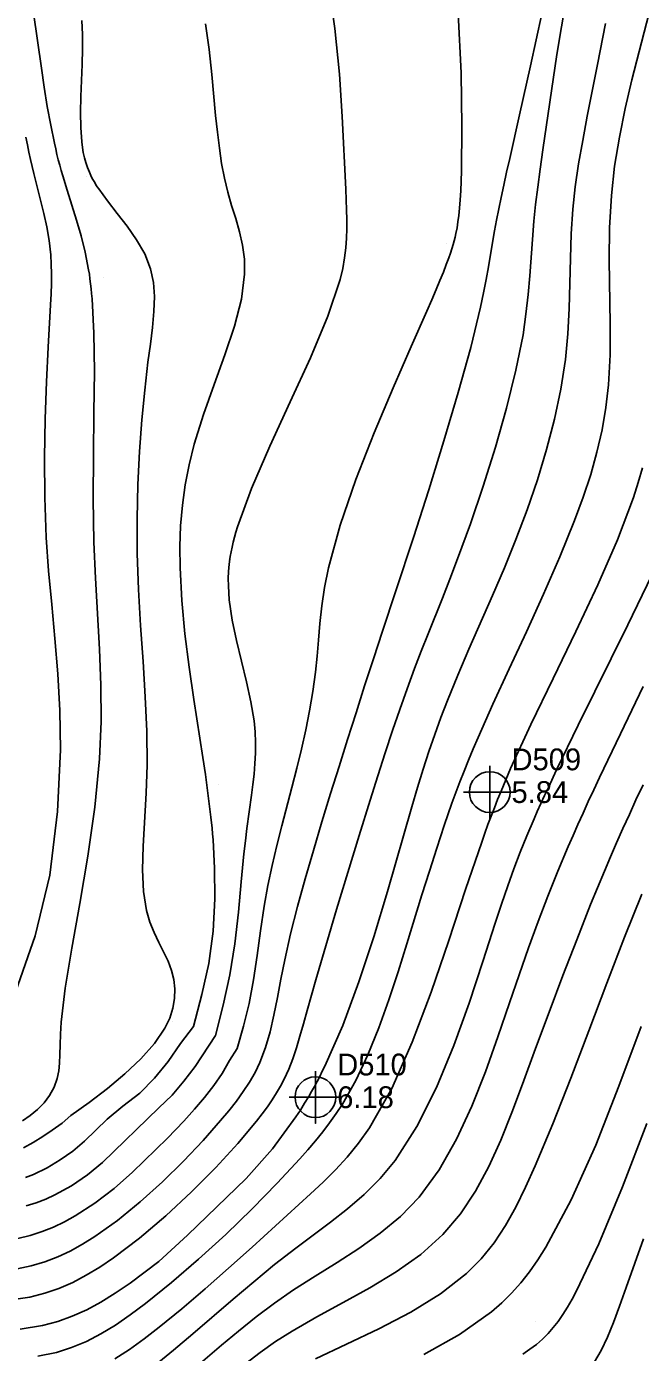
# Model space of a CAD drawing. Extents: x 2356077 to 2359823, y 225951 to 227822.
# Drawn here: x 2356980.4 to 2357050.9, y 226841 to 226993.2 of the extents above; entities that cross this region are included whole.
import ezdxf

# ---------------------------------------------------------------- set-up
doc = ezdxf.new("R2010")
doc.units = 0
for name, color, linetype in [('DTM Contours Major', 7, 'Continuous'), ('DTM Contours Minor', 7, 'Continuous'), ('Exist DTM Regular Point CELL', 7, 'Continuous'), ('Exist DTM Regular Point Cogo Elevation', 7, 'Continuous'), ('Exist DTM Regular Point Cogo Number', 7, 'Continuous'), ('PH Exist DTM Point', 7, 'Continuous')]:
    doc.layers.add(name, color=color, linetype=linetype)

msp = doc.modelspace()

# ---------------------------------------------------------------- linework, layer by layer
at = {"layer": 'DTM Contours Major'}
for points in [[(2357015.01, 226998.28), (2357015.79, 226992.92), (2357016.3, 226987.69), (2357016.61, 226982.83), (2357017.04, 226974.49), (2357017.09, 226973.29), (2357017.13, 226972.14), (2357017.15, 226971.02), (2357017.15, 226969.95), (2357017.12, 226968.88), (2357017.04, 226967.77), (2357016.9, 226966.62), (2357016.68, 226965.41), (2357016.38, 226964.12), (2357014.97, 226959.92), (2357012.97, 226955.16), (2357010.66, 226950.1), (2357008.32, 226945), (2357006.2, 226940.13), (2357004.6, 226935.75), (2357004.42, 226935.14), (2357004.25, 226934.55), (2357004.1, 226933.98), (2357003.98, 226933.42), (2357003.86, 226932.87), (2357003.77, 226932.33), (2357003.65, 226931.47), (2357003.58, 226930.63), (2357003.54, 226929.81), (2357003.55, 226928.99), (2357003.59, 226928.17), (2357003.66, 226927.36), (2357004, 226925.04), (2357004.49, 226922.69), (2357005.06, 226920.32), (2357005.64, 226917.97), (2357006.15, 226915.68), (2357006.51, 226913.48), (2357006.63, 226912.21), (2357006.68, 226910.98), (2357006.67, 226909.77), (2357006.61, 226908.57), (2357006.51, 226907.37), (2357006.38, 226906.16), (2357006.22, 226904.96), (2357005.69, 226901.12), (2357005.51, 226899.71), (2357005.34, 226898.22), (2357005.03, 226894.99), (2357004.71, 226891.51), (2357004.3, 226887.91), (2357003.73, 226884.32), (2357002.94, 226880.87), (2357002.07, 226877.37), (2356999.72, 226873.83), (2356998.45, 226872.12), (2356997.09, 226870.51), (2356995.58, 226869.08), (2356989.1, 226862.81), (2356987.37, 226861.39), (2356985.55, 226860.14), (2356983.64, 226859.08), (2356982.58, 226858.59), (2356981.49, 226858.17), (2356980.34, 226857.81)], [(2357052.41, 226996.83), (2357050.72, 226990.3), (2357049.9, 226987.04), (2357049.13, 226983.76), (2357048.45, 226980.45), (2357047.91, 226977.12), (2357047.53, 226973.76), (2357047.33, 226970.06), (2357047.3, 226966.36), (2357047.4, 226959.05), (2357047.38, 226955.5), (2357047.2, 226952.06), (2357046.9, 226949.44), (2357046.46, 226946.88), (2357045.88, 226944.33), (2357045.16, 226941.77), (2357044.3, 226939.16), (2357043.31, 226936.48), (2357041.63, 226932.31), (2357039.75, 226928.02), (2357037.77, 226923.7), (2357035.8, 226919.45), (2357033.92, 226915.38), (2357032.23, 226911.59), (2357031.66, 226910.26), (2357031.13, 226908.97), (2357030.62, 226907.72), (2357030.14, 226906.48), (2357029.68, 226905.25), (2357029.23, 226904.02), (2357028.34, 226901.49), (2357027.48, 226898.89), (2357026.63, 226896.23), (2357025.78, 226893.51), (2357024.05, 226887.91), (2357023.04, 226884.69), (2357021.98, 226881.45), (2357020.83, 226878.25), (2357019.58, 226875.16), (2357018.19, 226872.22), (2357016.65, 226869.5), (2357015.93, 226868.41), (2357015.18, 226867.35), (2357014.39, 226866.32), (2357013.56, 226865.3), (2357012.69, 226864.27), (2357011.77, 226863.23), (2357009.15, 226860.41), (2357006.28, 226857.49), (2357003.25, 226854.55), (2357000.14, 226851.7), (2356997.04, 226849.02), (2356994.03, 226846.6), (2356992.29, 226845.3), (2356990.59, 226844.15), (2356988.92, 226843.13), (2356987.25, 226842.26), (2356985.55, 226841.55), (2356983.81, 226841), (2356981.67, 226840.56)], [(2357051.03, 226893.61), (2357049.06, 226888.66), (2357047.03, 226883.36), (2357044.95, 226877.9), (2357042.86, 226872.46), (2357040.8, 226867.24), (2357038.79, 226862.43), (2357037.68, 226859.96), (2357036.56, 226857.67), (2357035.37, 226855.55), (2357034.06, 226853.58), (2357032.59, 226851.76), (2357030.91, 226850.07), (2357027.91, 226847.73), (2357024.49, 226845.63), (2357020.84, 226843.72), (2357017.13, 226841.94), (2357013.54, 226840.25)]]:
    msp.add_lwpolyline(points, dxfattribs=at)
at = {"layer": 'DTM Contours Minor'}
for points in [[(2357042.35, 226996.36), (2357041.29, 226989.94), (2357039.68, 226979.01), (2357039.36, 226976.79), (2357039.08, 226974.71), (2357038.83, 226972.73), (2357038.63, 226970.81), (2357038.46, 226968.74), (2357038.17, 226964.57), (2357037.98, 226962.42), (2357037.73, 226960.17), (2357037.39, 226957.8), (2357036.58, 226953.72), (2357035.51, 226949.37), (2357034.24, 226944.9), (2357032.83, 226940.43), (2357031.36, 226936.11), (2357029.88, 226932.06), (2357029, 226929.76), (2357028.14, 226927.58), (2357026.49, 226923.47), (2357025.7, 226921.48), (2357024.93, 226919.49), (2357024.07, 226917.17), (2357023.23, 226914.8), (2357022.4, 226912.36), (2357021.56, 226909.82), (2357020.71, 226907.17), (2357019.83, 226904.39), (2357018.56, 226900.31), (2357017.26, 226896.08), (2357015.97, 226891.82), (2357014.74, 226887.68), (2357013.6, 226883.78), (2357012.6, 226880.25), (2357012.17, 226878.73), (2357011.77, 226877.31), (2357011.37, 226875.97), (2357010.94, 226874.71), (2357010.48, 226873.51), (2357009.96, 226872.36), (2357009.55, 226871.56), (2357009.09, 226870.78), (2357008.59, 226869.99), (2357008.05, 226869.19), (2357007.45, 226868.38), (2357006.8, 226867.54), (2357004.64, 226864.96), (2357002.12, 226862.21), (2356999.33, 226859.42), (2356996.38, 226856.68), (2356993.36, 226854.12), (2356990.37, 226851.86), (2356988.8, 226850.8), (2356987.24, 226849.86), (2356985.68, 226849.04), (2356984.09, 226848.35), (2356982.46, 226847.79), (2356980.76, 226847.36), (2356977.77, 226846.94)], [(2357039.53, 226994.61), (2357038.25, 226988.67), (2357036.99, 226983.03), (2357035.86, 226978.03), (2357035.5, 226976.44), (2357035.18, 226974.95), (2357034.88, 226973.56), (2357034.61, 226972.23), (2357034.36, 226970.96), (2357034.13, 226969.71), (2357033.89, 226968.36), (2357033.42, 226965.59), (2357033.15, 226964.13), (2357032.85, 226962.59), (2357032.5, 226960.95), (2357031.38, 226956.33), (2357029.94, 226951.15), (2357028.31, 226945.63), (2357026.56, 226940.01), (2357024.8, 226934.52), (2357022.79, 226928.41), (2357021.25, 226923.76), (2357020.21, 226920.6), (2357019.2, 226917.49), (2357018.21, 226914.41), (2357017.23, 226911.34), (2357016.26, 226908.25), (2357015.28, 226905.13), (2357014.29, 226901.89), (2357013.31, 226898.62), (2357012.37, 226895.37), (2357011.49, 226892.16), (2357010.7, 226889.04), (2357010.03, 226886.05), (2357009.59, 226883.84), (2357009.19, 226881.73), (2357008.79, 226879.72), (2357008.35, 226877.8), (2357007.82, 226875.99), (2357007.17, 226874.28), (2357006.62, 226873.13), (2357005.98, 226872.02), (2357005.27, 226870.93), (2357004.48, 226869.84), (2357003.61, 226868.74), (2357002.66, 226867.61), (2357000.64, 226865.32), (2356998.39, 226862.95), (2356995.98, 226860.58), (2356993.44, 226858.28), (2356990.83, 226856.16), (2356988.21, 226854.29), (2356986.8, 226853.41), (2356985.39, 226852.63), (2356983.95, 226851.96), (2356982.47, 226851.4), (2356980.92, 226850.94), (2356979.3, 226850.59)], [(2357029.93, 226994.66), (2357030.27, 226987.86), (2357030.38, 226981.69), (2357030.32, 226976.62), (2357030.28, 226975.41), (2357030.24, 226974.32), (2357030.17, 226973.26), (2357030.1, 226972.32), (2357030.02, 226971.49), (2357029.92, 226970.74), (2357029.81, 226970.06), (2357029.68, 226969.43), (2357029.58, 226968.99), (2357029.47, 226968.56), (2357029.35, 226968.13), (2357029.21, 226967.66), (2357029.05, 226967.16), (2357028.86, 226966.63), (2357028.58, 226965.85), (2357028.24, 226964.99), (2357027.85, 226964.03), (2357027.41, 226962.98), (2357026.91, 226961.8), (2357026.34, 226960.51), (2357024.55, 226956.45), (2357022.47, 226951.71), (2357020.29, 226946.53), (2357018.2, 226941.18), (2357016.39, 226935.94), (2357015.06, 226931.05), (2357014.61, 226928.79), (2357014.29, 226926.67), (2357014.06, 226924.66), (2357013.89, 226922.74), (2357013.73, 226920.89), (2357013.55, 226919.07), (2357013.26, 226916.85), (2357012.88, 226914.64), (2357012.44, 226912.45), (2357011.95, 226910.25), (2357011.41, 226908.05), (2357010.84, 226905.83), (2357009.69, 226901.43), (2357009.12, 226899.18), (2357008.59, 226896.9), (2357008.09, 226894.57), (2357007.66, 226892.2), (2357007.23, 226889.38), (2357006.84, 226886.55), (2357006.43, 226883.75), (2357005.93, 226881.03), (2357005.29, 226878.45), (2357004.57, 226875.89), (2357003.7, 226874.49), (2357002.84, 226873.02), (2357001.87, 226871.62), (2357000.8, 226870.26), (2356999.65, 226868.91), (2356998.43, 226867.56), (2356996.57, 226865.59), (2356992.53, 226861.68), (2356990.42, 226859.82), (2356988.21, 226858.14), (2356985.96, 226856.67), (2356984.72, 226855.99), (2356983.47, 226855.39), (2356982.17, 226854.87), (2356980.81, 226854.44), (2356979.39, 226854.09)], [(2357046.87, 226993.5), (2357045.95, 226988.81), (2357044.77, 226982.86), (2357044.24, 226980.09), (2357043.77, 226977.4), (2357043.39, 226974.78), (2357043.11, 226972.19), (2357042.93, 226969.36), (2357042.83, 226966.53), (2357042.77, 226963.68), (2357042.7, 226960.8), (2357042.54, 226957.89), (2357042.26, 226954.94), (2357041.74, 226951.53), (2357041.01, 226948.09), (2357040.1, 226944.62), (2357039.04, 226941.15), (2357037.86, 226937.7), (2357036.57, 226934.31), (2357035.25, 226931.06), (2357033.88, 226927.87), (2357031.17, 226921.71), (2357029.89, 226918.72), (2357028.7, 226915.8), (2357027.96, 226913.86), (2357027.26, 226911.93), (2357026.59, 226909.96), (2357025.94, 226907.94), (2357025.29, 226905.83), (2357024.63, 226903.61), (2357021.83, 226893.91), (2357020.25, 226888.71), (2357018.54, 226883.52), (2357016.68, 226878.51), (2357014.64, 226873.87), (2357014.34, 226873.27), (2357014.04, 226872.68), (2357013.74, 226872.09), (2357013.43, 226871.52), (2357013.11, 226870.95), (2357012.78, 226870.38), (2357012.31, 226869.6), (2357011.82, 226868.82), (2357011.31, 226868.04), (2357008.63, 226864.38), (2357005.6, 226860.98), (2356998.86, 226854.45), (2356995.56, 226851.42), (2356992.27, 226848.95), (2356990.57, 226847.8), (2356988.92, 226846.78), (2356987.28, 226845.9), (2356985.63, 226845.15), (2356983.95, 226844.55), (2356982.22, 226844.1), (2356979.66, 226843.69)], [(2356981.18, 226994.75), (2356982.08, 226988.39), (2356982.41, 226986.2), (2356982.76, 226984), (2356983.15, 226981.84), (2356983.57, 226979.77), (2356983.72, 226979.12), (2356983.87, 226978.49), (2356984.02, 226977.87), (2356984.19, 226977.25), (2356984.36, 226976.64), (2356984.53, 226976.03), (2356985.05, 226974.37), (2356985.59, 226972.68), (2356986.13, 226970.96), (2356986.65, 226969.16), (2356987.12, 226967.27), (2356987.5, 226965.26), (2356987.59, 226964.73), (2356987.66, 226964.2), (2356987.73, 226963.64), (2356987.8, 226963.08), (2356987.85, 226962.51), (2356987.91, 226961.92), (2356988.11, 226957.97), (2356988.16, 226953.59), (2356988.12, 226948.88), (2356988.05, 226943.98), (2356988.02, 226938.98), (2356988.1, 226934), (2356988.28, 226929.86), (2356988.75, 226921.69), (2356988.91, 226917.59), (2356988.94, 226913.41), (2356988.77, 226909.12), (2356988.23, 226903.57), (2356987.43, 226897.97), (2356986.49, 226892.51), (2356985.57, 226887.38), (2356984.81, 226882.79), (2356984.34, 226878.91), (2356984.26, 226877.54), (2356984.22, 226876.31), (2356984.2, 226875.21), (2356984.16, 226874.21), (2356984.08, 226873.3), (2356983.91, 226872.45), (2356983.55, 226871.44), (2356983.03, 226870.5), (2356982.38, 226869.65), (2356981.62, 226868.88), (2356980.78, 226868.19), (2356979.9, 226867.57)], [(2356986.71, 226993.85), (2356986.76, 226993.05), (2356986.79, 226992.24), (2356986.8, 226991.43), (2356986.8, 226990.61), (2356986.76, 226988.81), (2356986.62, 226985.12), (2356986.58, 226983.3), (2356986.6, 226981.56), (2356986.71, 226979.92), (2356986.79, 226979.29), (2356986.89, 226978.69), (2356987.02, 226978.11), (2356987.18, 226977.54), (2356987.37, 226976.98), (2356987.59, 226976.44), (2356987.77, 226976.05), (2356987.93, 226975.73), (2356988.06, 226975.49), (2356988.2, 226975.25), (2356988.35, 226975.01), (2356988.5, 226974.77), (2356988.66, 226974.53), (2356989.67, 226973.15), (2356990.79, 226971.72), (2356991.94, 226970.24), (2356993.02, 226968.69), (2356993.94, 226967.06), (2356994.62, 226965.34), (2356994.94, 226963.79), (2356995.06, 226962.17), (2356995.01, 226960.45), (2356994.84, 226958.63), (2356994.6, 226956.71), (2356994.32, 226954.66), (2356993.94, 226951.45), (2356993.61, 226948.01), (2356993.34, 226944.38), (2356993.15, 226940.59), (2356993.06, 226936.68), (2356993.08, 226932.7), (2356993.24, 226928.56), (2356993.48, 226924.42), (2356993.76, 226920.3), (2356994.01, 226916.25), (2356994.18, 226912.28), (2356994.22, 226908.45), (2356994.12, 226905.18), (2356993.78, 226899.12), (2356993.71, 226896.4), (2356993.8, 226893.91), (2356994.15, 226891.7), (2356994.54, 226890.39), (2356995.03, 226889.18), (2356995.57, 226888.05), (2356996.12, 226886.97), (2356996.62, 226885.91), (2356997.02, 226884.85), (2356997.29, 226883.8), (2356997.41, 226882.73), (2356997.38, 226881.63), (2356997.19, 226880.51), (2356996.82, 226879.37), (2356996.26, 226878.22), (2356995.05, 226876.46), (2356993.49, 226874.71), (2356991.66, 226872.98), (2356989.68, 226871.3), (2356987.58, 226869.7), (2356985.46, 226868.19), (2356984.47, 226867.33), (2356983.33, 226866.52), (2356982.23, 226865.77), (2356981.12, 226865.08), (2356980.01, 226864.47)], [(2357000.93, 226993.46), (2357001.33, 226990.53), (2357001.64, 226987.67), (2357002.08, 226982.94), (2357002.29, 226981.04), (2357002.52, 226979.21), (2357002.78, 226977.46), (2357003.1, 226975.77), (2357003.49, 226974.14), (2357003.93, 226972.62), (2357004.39, 226971.12), (2357004.82, 226969.61), (2357005.17, 226968.06), (2357005.39, 226966.45), (2357005.42, 226964.75), (2357005.05, 226961.87), (2357004.24, 226958.76), (2357003.15, 226955.48), (2357001.93, 226952.09), (2357000.71, 226948.65), (2356999.64, 226945.23), (2356999.05, 226942.88), (2356998.6, 226940.55), (2356998.28, 226938.22), (2356998.07, 226935.87), (2356997.98, 226933.48), (2356998, 226931.03), (2356998.2, 226927.28), (2356998.57, 226923.45), (2356999.05, 226919.64), (2356999.59, 226915.95), (2357000.63, 226909.28), (2357000.91, 226907.33), (2357001.17, 226905.48), (2357001.4, 226903.66), (2357001.54, 226902.43), (2357001.68, 226901.16), (2357001.74, 226900.5), (2357001.8, 226899.82), (2357001.97, 226896.58), (2357001.99, 226893.04), (2357001.79, 226889.35), (2357001.31, 226885.64), (2357000.49, 226882.06), (2356999.56, 226878.42), (2356998.07, 226876.46), (2356996.65, 226874.38), (2356995.08, 226872.49), (2356993.4, 226870.75), (2356991.43, 226869.28), (2356989.63, 226867.78), (2356987.02, 226865.24), (2356985.69, 226864.1), (2356984.24, 226863.09), (2356982.74, 226862.2), (2356981.16, 226861.42), (2356980.27, 226861.06)], [(2356980.31, 226980.45), (2356980.48, 226979.59), (2356980.65, 226978.75), (2356980.83, 226977.92), (2356981.01, 226977.1), (2356981.21, 226976.28), (2356981.59, 226974.77), (2356981.98, 226973.25), (2356982.36, 226971.72), (2356982.7, 226970.17), (2356982.97, 226968.59), (2356983.15, 226966.97), (2356983.22, 226965.9), (2356983.24, 226964.8), (2356983.23, 226963.67), (2356983.19, 226962.48), (2356983.13, 226961.23), (2356982.87, 226956.35), (2356982.67, 226952.39), (2356982.51, 226948.13), (2356982.43, 226943.68), (2356982.46, 226939.11), (2356982.63, 226934.54), (2356982.91, 226930.69), (2356983.27, 226926.85), (2356983.64, 226922.93), (2356983.97, 226918.89), (2356984.19, 226914.66), (2356984.26, 226910.16), (2356983.94, 226903.09), (2356983.05, 226895.79), (2356981.38, 226888.8), (2356979.09, 226882.34)], [(2357051.1, 226942.5), (2357050.63, 226940.82), (2357050.08, 226939.1), (2357048.25, 226934.27), (2357045.99, 226929.11), (2357043.46, 226923.75), (2357040.84, 226918.35), (2357038.28, 226913.05), (2357035.96, 226908), (2357035.4, 226906.7), (2357034.86, 226905.42), (2357034.47, 226904.47), (2357034.1, 226903.51), (2357033.73, 226902.55), (2357033.36, 226901.57), (2357033, 226900.58), (2357032.64, 226899.57), (2357030.79, 226894.13), (2357028.87, 226888.29), (2357026.84, 226882.36), (2357024.67, 226876.6), (2357022.32, 226871.31), (2357019.76, 226866.77), (2357018.51, 226865), (2357017.21, 226863.41), (2357015.85, 226861.94), (2357014.45, 226860.55), (2357013, 226859.2), (2357006.28, 226853.1), (2357003.58, 226850.68), (2357000.88, 226848.29), (2356998.21, 226846.01), (2356995.62, 226843.89), (2356993.89, 226842.55), (2356992.2, 226841.34), (2356990.53, 226840.25)], [(2357052.17, 226930.21), (2357049.41, 226924.52), (2357043.73, 226912.98), (2357041.25, 226907.86), (2357040.3, 226905.85), (2357039.85, 226904.9), (2357039.43, 226903.99), (2357039.03, 226903.09), (2357038.65, 226902.22), (2357037.83, 226900.29), (2357037.07, 226898.4), (2357036.35, 226896.49), (2357035.64, 226894.53), (2357034.93, 226892.46), (2357034.2, 226890.25), (2357032.79, 226885.86), (2357031.21, 226881.1), (2357029.44, 226876.21), (2357027.45, 226871.4), (2357025.21, 226866.93), (2357022.7, 226863.03), (2357020.97, 226860.96), (2357019.15, 226859.13), (2357017.25, 226857.49), (2357015.29, 226855.96), (2357011.29, 226852.98), (2357008.86, 226851.09), (2357006.46, 226849.11), (2357004.09, 226847.1), (2356999.48, 226843.14), (2356997.27, 226841.27), (2356995.55, 226839.88)], [(2357051.19, 226917.42), (2357048.57, 226912), (2357046.19, 226907), (2357045.52, 226905.57), (2357044.88, 226904.21), (2357044.28, 226902.88), (2357043.7, 226901.6), (2357043.13, 226900.33), (2357042.59, 226899.08), (2357041.4, 226896.24), (2357040.25, 226893.37), (2357039.13, 226890.45), (2357038.03, 226887.45), (2357036.93, 226884.35), (2357035.82, 226881.14), (2357034.49, 226877.22), (2357033.07, 226873.22), (2357031.52, 226869.27), (2357029.76, 226865.47), (2357027.76, 226861.95), (2357025.46, 226858.82), (2357023.31, 226856.61), (2357020.99, 226854.67), (2357018.54, 226852.94), (2357016.03, 226851.33), (2357013.51, 226849.77), (2357011.05, 226848.2), (2357008.85, 226846.66), (2357006.75, 226845.07), (2357004.72, 226843.45), (2357002.75, 226841.82), (2356999, 226838.61)], [(2357051.17, 226906.15), (2357050.36, 226904.42), (2357049.6, 226902.75), (2357048.86, 226901.11), (2357048.14, 226899.5), (2357047.43, 226897.88), (2357046.73, 226896.24), (2357045.14, 226892.39), (2357043.55, 226888.37), (2357041.96, 226884.25), (2357040.39, 226880.07), (2357038.84, 226875.9), (2357037.32, 226871.8), (2357036.09, 226868.52), (2357034.83, 226865.35), (2357033.47, 226862.34), (2357031.95, 226859.51), (2357030.21, 226856.89), (2357028.19, 226854.52), (2357025.65, 226852.25), (2357022.81, 226850.24), (2357019.8, 226848.42), (2357016.73, 226846.73), (2357013.71, 226845.1), (2357010.86, 226843.46), (2357008.98, 226842.24), (2357007.21, 226841), (2357005.55, 226839.73)], [(2357050.95, 226878.42), (2357048.41, 226871.54), (2357045.74, 226864.8), (2357042.93, 226858.53), (2357040, 226853.09), (2357039.08, 226851.63), (2357038.12, 226850.27), (2357037.13, 226849), (2357036.08, 226847.82), (2357034.97, 226846.7), (2357033.77, 226845.65), (2357030.11, 226843.05), (2357026, 226840.77)], [(2357051.61, 226867.29), (2357048.8, 226860.01), (2357046.1, 226853.47), (2357043.58, 226848.13), (2357043.04, 226847.12), (2357042.5, 226846.2), (2357041.97, 226845.35), (2357041.43, 226844.57), (2357040.86, 226843.85), (2357040.28, 226843.18), (2357039.62, 226842.53), (2357038.92, 226841.93), (2357038.17, 226841.36), (2357037.37, 226840.82)], [(2357051.22, 226854.02), (2357049.23, 226848.45), (2357048.48, 226846.33), (2357047.78, 226844.43), (2357047.09, 226842.74), (2357046.38, 226841.24), (2357045.59, 226839.92)]]:
    msp.add_lwpolyline(points, dxfattribs=at)
at = {"layer": 'Exist DTM Regular Point CELL'}
for points in [[(2357033.57, 226908.31), (2357033.57, 226902.31), (2357033.57, 226905.31), (2357036.57, 226905.31), (2357030.57, 226905.31)], [(2357013.55, 226873.29), (2357013.55, 226867.29), (2357013.55, 226870.29), (2357016.55, 226870.29), (2357010.55, 226870.29)]]:
    msp.add_lwpolyline(points, dxfattribs=at)
for centre in [(2357033.57, 226905.31), (2357013.55, 226870.29)]:
    msp.add_circle(centre, 2.34, dxfattribs=at)
at = {"layer": 'PH Exist DTM Point'}
for p, q in [((2356987.21, 226975.98), (2356987.21, 226975.98)), ((2357028.59, 226968.31), (2357028.59, 226968.31)), ((2356989.17, 226964.33), (2356989.17, 226964.33)), ((2357003.55, 226932.03), (2357003.55, 226932.03)), ((2357021.07, 226926.05), (2357021.07, 226926.05)), ((2357002.41, 226906.14), (2357002.41, 226906.14)), ((2356997.14, 226878.97), (2356997.14, 226878.97)), ((2357038.87, 226844.5), (2357038.87, 226844.5))]:
    msp.add_line(p, q, dxfattribs=at)

# ---------------------------------------------------------------- texts
at = {"layer": 'Exist DTM Regular Point Cogo Elevation'}
for s, p in [('5.84', (2357036.07, 226904.06)), ('6.18', (2357016.05, 226869.04))]:
    msp.add_text(s, height=2.5, dxfattribs=at).set_placement(p)
at = {"layer": 'Exist DTM Regular Point Cogo Number'}
for s, p in [('D509', (2357036.07, 226907.81)), ('D510', (2357016.05, 226872.79))]:
    msp.add_text(s, height=2.5, dxfattribs=at).set_placement(p)

doc.saveas('drawing.dxf')
